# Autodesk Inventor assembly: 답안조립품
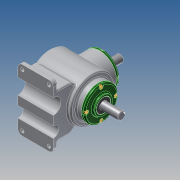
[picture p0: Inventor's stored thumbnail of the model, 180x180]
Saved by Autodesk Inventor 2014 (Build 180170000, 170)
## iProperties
Created: 2018-08
Part Number: 답안조립품
Document SubType Name: Assembly
Designer: kb542
Author: kb542
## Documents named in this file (14)
- C:\Users\kb542\Desktop\480807V1017\답안조립품.iam
- C:\Users\kb542\Desktop\480807V1017\본체.ipt
- C:\Users\kb542\Desktop\480807V1017\메인 베벨기어.ipt
- C:\Users\kb542\Desktop\480807V1017\메인 축.ipt
- 메인 축.ipt
- C:\Users\kb542\Desktop\480807V1017\베어링 6203.ipt
- C:\Users\kb542\Desktop\480807V1017\볼트 M4.ipt
- C:\Users\kb542\Desktop\480807V1017\서브 베벨기어.ipt
- C:\Users\kb542\Desktop\480807V1017\서브 축.ipt
- 서브 축.ipt
- C:\Users\kb542\Desktop\480807V1017\오일실 17 32 8.ipt
- C:\Users\kb542\Desktop\480807V1017\커버.ipt
- C:\Users\kb542\Desktop\480807V1017\키 4x4.ipt
- C:\Users\kb542\Desktop\480807V1017\키 5x5.ipt
